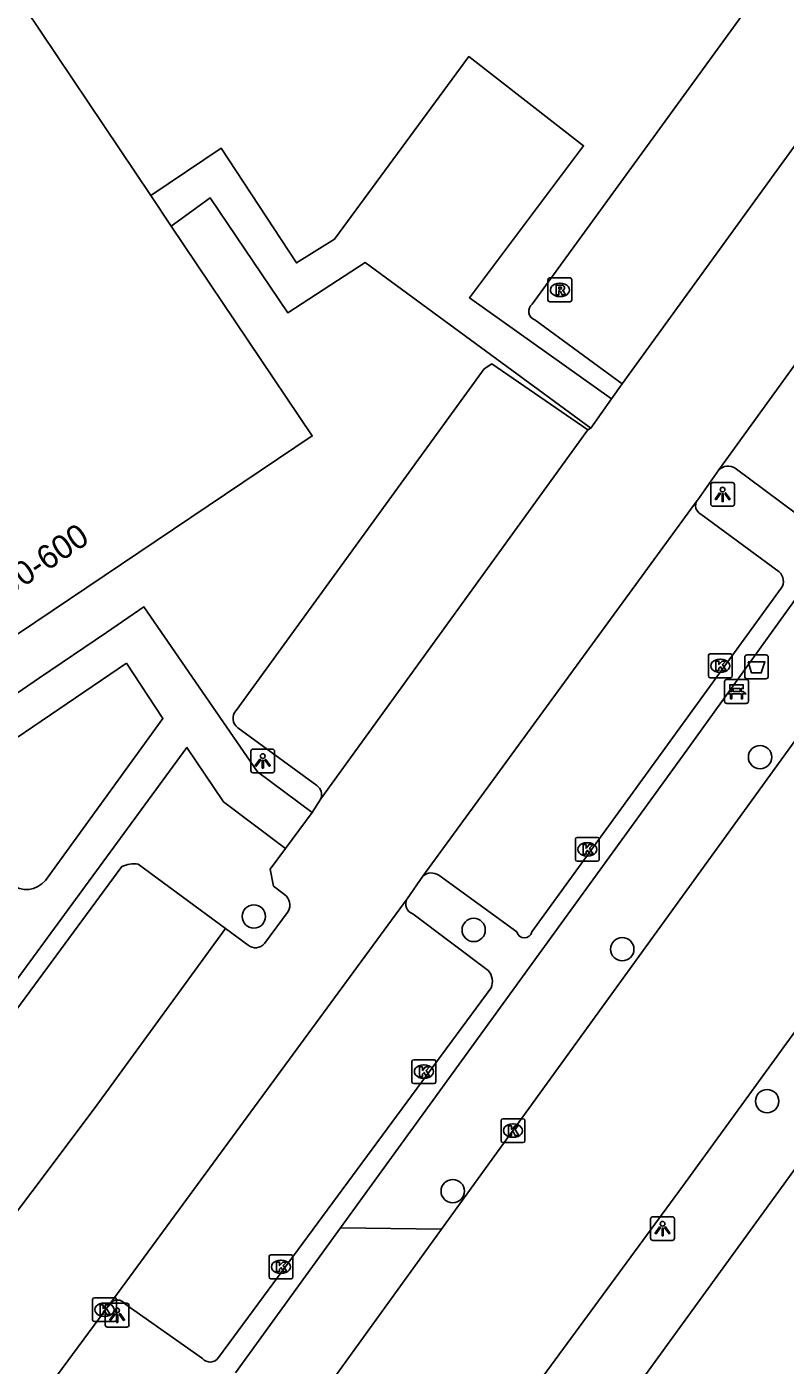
# Model space of a CAD drawing. Extents: x 159675 to 160530, y 382179 to 382901.
# Drawn here: x 159972.5 to 160004.3, y 382438.2 to 382494.4 of the extents above; entities that cross this region are included whole.
import ezdxf

# ---------------------------------------------------------------- set-up
doc = ezdxf.new("R2010")
doc.units = 0
for name, color, linetype in [('IMGEO_Afvalbak', 7, 'Continuous'), ('IMGEO_Bank', 7, 'Continuous'), ('IMGEO_Boom', 7, 'Continuous'), ('IMGEO_Kolk', 7, 'Continuous'), ('IMGEO_Lichtpunt', 7, 'Continuous'), ('IMGEO_Pand', 7, 'Continuous'), ('IMGEO_Pand_nummerreeks', 7, 'Continuous'), ('IMGEO_Parkeervlak_open', 7, 'Continuous'), ('IMGEO_Rijbaan_lokaal_open', 7, 'Continuous'), ('IMGEO_Rioolput', 7, 'Continuous'), ('IMGEO_Voetpad_gesloten', 7, 'Continuous'), ('IMGEO_Voetpad_open', 7, 'Continuous')]:
    doc.layers.add(name, color=color, linetype=linetype)

msp = doc.modelspace()

# ---------------------------------------------------------------- linework, layer by layer
at = {"layer": 'IMGEO_Afvalbak'}
for p, q in [((160002.607, 382467.102), (160002.607, 382467.902)), ((160002.607, 382467.902), (160002.607, 382467.102)), ((160002.707, 382468.002), (160003.497, 382468.002)), ((160003.497, 382468.002), (160002.707, 382468.002)), ((160003.597, 382467.902), (160003.597, 382467.102)), ((160003.597, 382467.102), (160003.597, 382467.902)), ((160003.497, 382467.002), (160002.707, 382467.002)), ((160002.707, 382467.002), (160003.497, 382467.002))]:
    msp.add_line(p, q, dxfattribs=at)
msp.add_lwpolyline([(160002.75, 382467.716), (160003.454, 382467.716), (160003.305, 382467.246), (160002.899, 382467.246), (160002.75, 382467.716)], dxfattribs=at)
for centre, start, end in [((160002.707, 382467.902), 90, 180), ((160002.707, 382467.902), 90, 180), ((160003.497, 382467.902), 0, 90), ((160003.497, 382467.902), 360, 90), ((160002.707, 382467.102), 180, 270), ((160002.707, 382467.102), 180, 270), ((160003.497, 382467.102), 270, 0), ((160003.497, 382467.102), 270, 0)]:
    msp.add_arc(centre, 0.1, start, end, dxfattribs=at)
at = {"layer": 'IMGEO_Bank'}
for p, q in [((160001.764, 382466.044), (160001.764, 382466.885)), ((160001.764, 382466.885), (160001.764, 382466.044)), ((160001.839, 382466.969), (160002.68, 382466.969)), ((160002.68, 382466.969), (160001.839, 382466.969)), ((160002.073, 382466.475), (160002.073, 382466.581)), ((160002.117, 382466.581), (160002.117, 382466.475)), ((160002.405, 382466.587), (160002.123, 382466.587)), ((160002.411, 382466.475), (160002.411, 382466.581)), ((160002.455, 382466.581), (160002.455, 382466.475)), ((160002.764, 382466.894), (160002.764, 382466.053)), ((160002.764, 382466.053), (160002.764, 382466.894)), ((160002.461, 382466.367), (160002.068, 382466.367)), ((160002.123, 382466.469), (160002.405, 382466.469)), ((160002.689, 382465.969), (160001.848, 382465.969)), ((160001.848, 382465.969), (160002.689, 382465.969))]:
    msp.add_line(p, q, dxfattribs=at)
for points in [[(160002.067, 382466.587), (160001.981, 382466.587), (160001.981, 382466.748), (160002.544, 382466.748), (160002.544, 382466.587), (160002.461, 382466.587)], [(160002.011, 382466.367), (160001.869, 382466.367), (160001.981, 382466.469), (160002.067, 382466.469)], [(160002.061, 382466.36), (160002.061, 382466.153), (160002.018, 382466.153), (160002.018, 382466.36)], [(160002.461, 382466.469), (160002.544, 382466.469), (160002.656, 382466.367), (160002.517, 382466.367)], [(160002.511, 382466.36), (160002.511, 382466.153), (160002.467, 382466.153), (160002.467, 382466.36)]]:
    msp.add_lwpolyline(points, dxfattribs=at)
for centre, radius, start, end in [((160001.842, 382466.891), 0.0779, 92.4484, 184.2845), ((160001.842, 382466.891), 0.0779, 92.4484, 184.2845), ((160002.066, 382466.58), 0.00671, 2.8957, 87.1043), ((160002.123, 382466.58), 0.00671, 92.8957, 177.1043), ((160002.405, 382466.58), 0.00671, 2.8957, 87.1043), ((160002.462, 382466.58), 0.00671, 92.8957, 177.1043), ((160002.686, 382466.891), 0.0779, 2.4484, 94.2845), ((160002.686, 382466.891), 0.0779, 2.4484, 94.2845), ((160001.842, 382466.047), 0.0779, 182.4484, 274.2845), ((160001.842, 382466.047), 0.0779, 182.4484, 274.2845), ((160002.011, 382466.36), 0.00671, 2.8957, 87.1043), ((160002.068, 382466.36), 0.00671, 92.8957, 177.1043), ((160002.066, 382466.476), 0.00671, 272.8957, 357.1043), ((160002.123, 382466.476), 0.00671, 182.8957, 267.1043), ((160002.405, 382466.476), 0.00671, 272.8957, 357.1043), ((160002.462, 382466.476), 0.00671, 182.8957, 267.1043), ((160002.46, 382466.36), 0.00671, 2.8957, 87.1043), ((160002.517, 382466.36), 0.00671, 92.8957, 177.1043), ((160002.686, 382466.047), 0.0779, 272.4484, 4.2845), ((160002.686, 382466.047), 0.0779, 272.4484, 4.2845)]:
    msp.add_arc(centre, radius, start, end, dxfattribs=at)
at = {"layer": 'IMGEO_Boom'}
for centre in [(160003.25, 382463.712), (159982.015, 382457.028), (159991.237, 382456.462), (159997.472, 382455.653), (160003.548, 382449.28), (159990.357, 382445.504)]:
    msp.add_circle(centre, 0.489, dxfattribs=at)
at = {"layer": 'IMGEO_Kolk'}
for p, q in [((160001.082, 382467.117), (160001.082, 382467.969)), ((160001.157, 382468.043), (160002.009, 382468.043)), ((160001.57, 382467.823), (160001.595, 382467.823)), ((160002.083, 382467.969), (160002.083, 382467.117)), ((160001.593, 382467.263), (160001.568, 382467.263)), ((160002.009, 382467.043), (160001.157, 382467.043)), ((159995.506, 382459.416), (159995.506, 382460.268)), ((159995.581, 382460.342), (159996.433, 382460.342)), ((159995.994, 382460.122), (159996.019, 382460.122)), ((159996.507, 382460.268), (159996.507, 382459.416)), ((159996.433, 382459.342), (159995.581, 382459.342)), ((159996.017, 382459.562), (159995.992, 382459.562)), ((159988.648, 382450.093), (159988.648, 382450.945)), ((159988.723, 382451.019), (159989.575, 382451.019)), ((159989.649, 382450.945), (159989.649, 382450.093)), ((159989.136, 382450.799), (159989.161, 382450.799)), ((159989.575, 382450.019), (159988.723, 382450.019)), ((159989.159, 382450.239), (159989.134, 382450.239)), ((159992.384, 382447.617), (159992.384, 382448.469)), ((159992.459, 382448.543), (159993.311, 382448.543)), ((159992.872, 382448.323), (159992.897, 382448.323)), ((159993.385, 382448.469), (159993.385, 382447.617)), ((159993.311, 382447.543), (159992.459, 382447.543)), ((159992.895, 382447.763), (159992.87, 382447.763)), ((159982.651, 382441.904), (159982.651, 382442.756)), ((159982.726, 382442.83), (159983.578, 382442.83)), ((159983.139, 382442.61), (159983.164, 382442.61)), ((159983.652, 382442.756), (159983.652, 382441.904)), ((159983.162, 382442.05), (159983.137, 382442.05)), ((159983.578, 382441.83), (159982.726, 382441.83)), ((159975.248, 382440.105), (159975.248, 382440.957)), ((159975.323, 382441.031), (159976.175, 382441.031)), ((159975.736, 382440.811), (159975.761, 382440.811)), ((159976.249, 382440.957), (159976.249, 382440.105)), ((159975.759, 382440.251), (159975.734, 382440.251)), ((159976.175, 382440.031), (159975.323, 382440.031))]:
    msp.add_line(p, q, dxfattribs=at)
for points in [[(160001.082, 382467.117), (160001.082, 382467.969)], [(160001.157, 382468.043), (160002.009, 382468.043)], [(160001.403, 382467.743), (160001.526, 382467.743), (160001.526, 382467.592), (160001.656, 382467.743), (160001.82, 382467.743), (160001.674, 382467.592), (160001.827, 382467.343), (160001.675, 382467.343), (160001.59, 382467.507), (160001.526, 382467.44), (160001.526, 382467.343), (160001.403, 382467.343), (160001.403, 382467.743)], [(160002.083, 382467.969), (160002.083, 382467.117)], [(160002.009, 382467.043), (160001.157, 382467.043)], [(159995.506, 382459.416), (159995.506, 382460.268)], [(159995.581, 382460.342), (159996.433, 382460.342)], [(159995.827, 382460.042), (159995.95, 382460.042), (159995.95, 382459.891), (159996.08, 382460.042), (159996.244, 382460.042), (159996.098, 382459.891), (159996.251, 382459.642), (159996.099, 382459.642), (159996.014, 382459.806), (159995.95, 382459.739), (159995.95, 382459.642), (159995.827, 382459.642), (159995.827, 382460.042)], [(159996.507, 382460.268), (159996.507, 382459.416)], [(159996.433, 382459.342), (159995.581, 382459.342)], [(159988.648, 382450.093), (159988.648, 382450.945)], [(159988.723, 382451.019), (159989.575, 382451.019)], [(159989.649, 382450.945), (159989.649, 382450.093)], [(159988.969, 382450.719), (159989.092, 382450.719), (159989.092, 382450.568), (159989.222, 382450.719), (159989.386, 382450.719), (159989.24, 382450.568), (159989.393, 382450.319), (159989.241, 382450.319), (159989.156, 382450.483), (159989.092, 382450.416), (159989.092, 382450.319), (159988.969, 382450.319), (159988.969, 382450.719)], [(159989.575, 382450.019), (159988.723, 382450.019)], [(159992.384, 382447.617), (159992.384, 382448.469)], [(159992.459, 382448.543), (159993.311, 382448.543)], [(159992.705, 382448.243), (159992.828, 382448.243), (159992.828, 382448.092), (159992.958, 382448.243), (159993.122, 382448.243), (159992.976, 382448.092), (159993.129, 382447.843), (159992.977, 382447.843), (159992.892, 382448.007), (159992.828, 382447.94), (159992.828, 382447.843), (159992.705, 382447.843), (159992.705, 382448.243)], [(159993.385, 382448.469), (159993.385, 382447.617)], [(159993.311, 382447.543), (159992.459, 382447.543)], [(159982.651, 382441.904), (159982.651, 382442.756)], [(159982.726, 382442.83), (159983.578, 382442.83)], [(159982.972, 382442.53), (159983.095, 382442.53), (159983.095, 382442.379), (159983.225, 382442.53), (159983.389, 382442.53), (159983.243, 382442.379), (159983.396, 382442.13), (159983.244, 382442.13), (159983.159, 382442.294), (159983.095, 382442.227), (159983.095, 382442.13), (159982.972, 382442.13), (159982.972, 382442.53)], [(159983.652, 382442.756), (159983.652, 382441.904)], [(159983.578, 382441.83), (159982.726, 382441.83)], [(159975.248, 382440.105), (159975.248, 382440.957)], [(159975.323, 382441.031), (159976.175, 382441.031)], [(159976.249, 382440.957), (159976.249, 382440.105)], [(159975.569, 382440.731), (159975.692, 382440.731), (159975.692, 382440.58), (159975.822, 382440.731), (159975.986, 382440.731), (159975.84, 382440.58), (159975.993, 382440.331), (159975.841, 382440.331), (159975.756, 382440.495), (159975.692, 382440.428), (159975.692, 382440.331), (159975.569, 382440.331), (159975.569, 382440.731)], [(159976.175, 382440.031), (159975.323, 382440.031)]]:
    msp.add_lwpolyline(points, dxfattribs=at)
for centre, start, end in [((160001.159, 382467.967), 91.552, 178.448), ((160001.159, 382467.967), 91.552, 178.448), ((160002.007, 382467.967), 1.552, 88.448), ((160002.007, 382467.967), 1.552, 88.448), ((160001.159, 382467.119), 181.552, 268.448), ((160001.159, 382467.119), 181.552, 268.448), ((160002.007, 382467.119), 271.552, 358.448), ((160002.007, 382467.119), 271.552, 358.448), ((159995.583, 382460.266), 91.552, 178.448), ((159995.583, 382460.266), 91.552, 178.448), ((159996.431, 382460.266), 1.552, 88.448), ((159996.431, 382460.266), 1.552, 88.448), ((159995.583, 382459.418), 181.552, 268.448), ((159995.583, 382459.418), 181.552, 268.448), ((159996.431, 382459.418), 271.552, 358.448), ((159996.431, 382459.418), 271.552, 358.448), ((159988.725, 382450.943), 91.552, 178.448), ((159988.725, 382450.943), 91.552, 178.448), ((159989.573, 382450.943), 1.552, 88.448), ((159989.573, 382450.943), 1.552, 88.448), ((159988.725, 382450.095), 181.552, 268.448), ((159988.725, 382450.095), 181.552, 268.448), ((159989.573, 382450.095), 271.552, 358.448), ((159989.573, 382450.095), 271.552, 358.448), ((159992.461, 382448.467), 91.552, 178.448), ((159992.461, 382448.467), 91.552, 178.448), ((159993.309, 382448.467), 1.552, 88.448), ((159993.309, 382448.467), 1.552, 88.448), ((159992.461, 382447.619), 181.552, 268.448), ((159992.461, 382447.619), 181.552, 268.448), ((159993.309, 382447.619), 271.552, 358.448), ((159993.309, 382447.619), 271.552, 358.448), ((159982.728, 382442.754), 91.552, 178.448), ((159982.728, 382442.754), 91.552, 178.448), ((159983.576, 382442.754), 1.552, 88.448), ((159983.576, 382442.754), 1.552, 88.448), ((159982.728, 382441.906), 181.552, 268.448), ((159982.728, 382441.906), 181.552, 268.448), ((159983.576, 382441.906), 271.552, 358.448), ((159983.576, 382441.906), 271.552, 358.448), ((159975.325, 382440.955), 91.552, 178.448), ((159975.325, 382440.955), 91.552, 178.448), ((159976.173, 382440.955), 1.552, 88.448), ((159976.173, 382440.955), 1.552, 88.448), ((159975.325, 382440.107), 181.552, 268.448), ((159975.325, 382440.107), 181.552, 268.448), ((159976.173, 382440.107), 271.552, 358.448), ((159976.173, 382440.107), 271.552, 358.448)]:
    msp.add_arc(centre, 0.0765, start, end, dxfattribs=at)
for centre, major_axis, ratio, start_param, end_param in [((160001.569, 382467.543), (-0.387, 0.002), 0.722429, 4.712389, 7.853982), ((160001.594, 382467.543), (-0.39, 0.002), 0.717154, 1.570796, 4.712389), ((159995.993, 382459.842), (-0.387, 0.002), 0.722429, 4.712389, 7.853982), ((159996.018, 382459.842), (-0.39, 0.002), 0.717154, 1.570796, 4.712389), ((159989.135, 382450.519), (-0.387, 0.002), 0.722429, 4.712389, 7.853982), ((159989.16, 382450.519), (-0.39, 0.002), 0.717154, 1.570796, 4.712389), ((159992.871, 382448.043), (-0.387, 0.002), 0.722429, 4.712389, 7.853982), ((159992.896, 382448.043), (-0.39, 0.002), 0.717154, 1.570796, 4.712389), ((159983.138, 382442.33), (-0.387, 0.002), 0.722429, 4.712389, 7.853982), ((159983.163, 382442.33), (-0.39, 0.002), 0.717154, 1.570796, 4.712389), ((159975.735, 382440.531), (-0.387, 0.002), 0.722429, 4.712389, 7.853982), ((159975.76, 382440.531), (-0.39, 0.002), 0.717154, 1.570796, 4.712389)]:
    msp.add_ellipse(centre, major_axis=major_axis, ratio=ratio, start_param=start_param, end_param=end_param, dxfattribs=at)
at = {"layer": 'IMGEO_Lichtpunt'}
for p, q in [((160001.181, 382475.138), (160001.181, 382474.331)), ((160001.181, 382475.138), (160001.181, 382474.331)), ((160002.083, 382475.233), (160001.275, 382475.233)), ((160002.083, 382475.233), (160001.275, 382475.233)), ((160002.177, 382474.331), (160002.177, 382475.138)), ((160002.177, 382474.331), (160002.177, 382475.138)), ((160001.275, 382474.237), (160002.083, 382474.237)), ((160001.275, 382474.237), (160002.083, 382474.237)), ((159981.89, 382463.956), (159981.89, 382463.149)), ((159981.89, 382463.956), (159981.89, 382463.149)), ((159982.792, 382464.051), (159981.984, 382464.051)), ((159982.792, 382464.051), (159981.984, 382464.051)), ((159982.886, 382463.149), (159982.886, 382463.956)), ((159982.886, 382463.149), (159982.886, 382463.956)), ((159981.984, 382463.055), (159982.792, 382463.055)), ((159981.984, 382463.055), (159982.792, 382463.055)), ((159998.662, 382444.338), (159998.662, 382443.531)), ((159998.662, 382444.338), (159998.662, 382443.531)), ((159999.564, 382444.433), (159998.756, 382444.433)), ((159999.564, 382444.433), (159998.756, 382444.433)), ((159999.658, 382443.531), (159999.658, 382444.338)), ((159999.658, 382443.531), (159999.658, 382444.338)), ((159998.756, 382443.437), (159999.564, 382443.437)), ((159998.756, 382443.437), (159999.564, 382443.437)), ((159976.683, 382440.798), (159975.875, 382440.798)), ((159976.683, 382440.798), (159975.875, 382440.798)), ((159975.781, 382440.703), (159975.781, 382439.896)), ((159975.781, 382440.703), (159975.781, 382439.896)), ((159976.777, 382439.896), (159976.777, 382440.703)), ((159976.777, 382439.896), (159976.777, 382440.703)), ((159975.875, 382439.802), (159976.683, 382439.802)), ((159975.875, 382439.802), (159976.683, 382439.802))]:
    msp.add_line(p, q, dxfattribs=at)
for points in [[(160001.555, 382474.802), (160001.594, 382474.774), (160001.406, 382474.512), (160001.368, 382474.539), (160001.555, 382474.802)], [(160001.657, 382474.754), (160001.704, 382474.754), (160001.704, 382474.432), (160001.657, 382474.432), (160001.657, 382474.754)], [(160001.767, 382474.774), (160001.805, 382474.801), (160001.992, 382474.539), (160001.953, 382474.511), (160001.767, 382474.774)], [(159982.264, 382463.62), (159982.303, 382463.592), (159982.115, 382463.33), (159982.077, 382463.357), (159982.264, 382463.62)], [(159982.366, 382463.572), (159982.413, 382463.572), (159982.413, 382463.25), (159982.366, 382463.25), (159982.366, 382463.572)], [(159982.476, 382463.592), (159982.514, 382463.619), (159982.701, 382463.357), (159982.662, 382463.329), (159982.476, 382463.592)], [(159999.036, 382444.002), (159999.075, 382443.974), (159998.887, 382443.712), (159998.849, 382443.739), (159999.036, 382444.002)], [(159999.138, 382443.954), (159999.185, 382443.954), (159999.185, 382443.632), (159999.138, 382443.632), (159999.138, 382443.954)], [(159999.248, 382443.974), (159999.286, 382444.001), (159999.473, 382443.739), (159999.434, 382443.711), (159999.248, 382443.974)], [(159976.155, 382440.367), (159976.194, 382440.339), (159976.006, 382440.077), (159975.968, 382440.104), (159976.155, 382440.367)], [(159976.257, 382440.319), (159976.304, 382440.319), (159976.304, 382439.997), (159976.257, 382439.997), (159976.257, 382440.319)], [(159976.367, 382440.339), (159976.405, 382440.366), (159976.592, 382440.104), (159976.553, 382440.076), (159976.367, 382440.339)]]:
    msp.add_lwpolyline(points, dxfattribs=at)
for centre in [(160001.68, 382474.936), (159982.389, 382463.754), (159999.161, 382444.136), (159976.28, 382440.501)]:
    msp.add_circle(centre, 0.0994, dxfattribs=at)
for centre, start, end in [((160001.275, 382475.138), 90, 180), ((160001.275, 382475.138), 90, 180), ((160002.083, 382475.138), 0, 90), ((160002.083, 382475.138), 0, 90), ((160001.275, 382474.331), 180, 270), ((160001.275, 382474.331), 180, 270), ((160002.083, 382474.331), 270, 0), ((160002.083, 382474.331), 270, 360), ((159981.984, 382463.956), 90, 180), ((159981.984, 382463.956), 90, 180), ((159982.792, 382463.956), 0, 90), ((159982.792, 382463.956), 0, 90), ((159981.984, 382463.149), 180, 270), ((159981.984, 382463.149), 180, 270), ((159982.792, 382463.149), 270, 0), ((159982.792, 382463.149), 270, 360), ((159998.756, 382444.338), 90, 180), ((159998.756, 382444.338), 90, 180), ((159999.564, 382444.338), 0, 90), ((159999.564, 382444.338), 0, 90), ((159998.756, 382443.531), 180, 270), ((159998.756, 382443.531), 180, 270), ((159999.564, 382443.531), 270, 0), ((159999.564, 382443.531), 270, 360), ((159975.875, 382440.703), 90, 180), ((159975.875, 382440.703), 90, 180), ((159976.683, 382440.703), 0, 90), ((159976.683, 382440.703), 0, 90), ((159975.875, 382439.896), 180, 270), ((159975.875, 382439.896), 180, 270), ((159976.683, 382439.896), 270, 0), ((159976.683, 382439.896), 270, 360)]:
    msp.add_arc(centre, 0.0946, start, end, dxfattribs=at)
at = {"layer": 'IMGEO_Pand'}
for points in [[(159953.275, 382483.094), (159952.337, 382484.474), (159971.108, 382497.075), (159977.69, 382487.272)], [(159978.552, 382485.987), (159977.69, 382487.272)], [(159978.552, 382485.987), (159984.462, 382477.186), (159972.103, 382468.865), (159965.701, 382464.59), (159959.223, 382474.207)]]:
    msp.add_lwpolyline(points, dxfattribs=at)
at = {"layer": 'IMGEO_Parkeervlak_open'}
for points in [[(159993.697, 382482.721), (160004.104, 382497.066)], [(159997.466, 382479.378), (159993.807, 382482.054)], [(159996.032, 382477.439), (159991.992, 382480.211), (159991.678, 382480.008), (159981.273, 382465.667)], [(160005.388, 382473.465), (160002.211, 382475.832)], [(160004.053, 382471.48), (160000.766, 382473.907)], [(159993.682, 382456.376), (160004.14, 382470.802)], [(159981.347, 382464.948), (159984.655, 382462.522)], [(159976.477, 382459.119), (159966.518, 382445.61)], [(159980.82, 382456.527), (159977.165, 382459.225)], [(159989.773, 382458.761), (159993.043, 382456.381)], [(159991.844, 382454.766), (159988.686, 382457.137)], [(159980.537, 382438.524), (159991.968, 382454.03)], [(159976.606, 382440.776), (159979.862, 382438.479)]]:
    msp.add_lwpolyline(points, dxfattribs=at)
for centre, radius, start, end in [((159993.933, 382482.417), 0.384, 127.8031, 250.9265), ((160001.907, 382475.331), 0.586, 58.7458, 131.7769), ((160000.944, 382474.26), 0.395, 146.4119, 243.2135), ((160003.725, 382471.093), 0.507, 324.9413, 49.6831), ((159981.608, 382465.338), 0.469, 135.4859, 236.2666), ((159984.385, 382462.135), 0.472, 339.1728, 55.0762), ((159976.987, 382458.095), 1.144, 81.0385, 116.4788), ((159989.467, 382458.298), 0.555, 56.5201, 130.0406), ((159988.817, 382457.551), 0.434, 150.1035, 252.3975), ((159993.363, 382456.455), 0.329, 193.0004, 346.1029), ((159991.318, 382454.299), 0.703, 337.5039, 41.6227), ((159976.293, 382440.551), 0.386, 35.705, 140.7386), ((159980.182, 382438.762), 0.427, 221.4849, 326.1432)]:
    msp.add_arc(centre, radius, start, end, dxfattribs=at)
at = {"layer": 'IMGEO_Rijbaan_lokaal_open'}
for points in [[(160008.707, 382494.883), (159997.466, 382479.378)], [(160001.516, 382475.768), (160012.741, 382491.261)], [(159989.893, 382443.905), (160000, 382457.874), (160020.333, 382485.978)], [(159997.466, 382479.378), (159997.019, 382478.745)], [(159997.019, 382478.745), (159996.152, 382477.512)], [(159996.032, 382477.439), (159984.826, 382461.967)], [(159996.152, 382477.512), (159996.032, 382477.439)], [(160000.615, 382474.478), (160000.638, 382474.511), (160001.516, 382475.768)], [(159989.11, 382458.723), (160000.615, 382474.478)], [(159984.826, 382461.967), (159984.461, 382461.389)], [(159984.461, 382461.389), (159983.343, 382459.872)], [(159983.343, 382459.872), (159982.702, 382459.015), (159982.838, 382458.301), (159983.301, 382457.947)], [(159988.441, 382457.767), (159989.11, 382458.723)], [(159975.994, 382440.795), (159988.441, 382457.767)], [(159983.452, 382457.239), (159982.467, 382455.892)], [(159980.82, 382456.527), (159975.319, 382448.954), (159970.077, 382441.998)], [(159981.771, 382455.825), (159980.82, 382456.527)], [(159984.695, 382424.782), (159986.94, 382427.882), (159990.318, 382432.531), (160000, 382445.699), (160006.199, 382454.224)], [(159989.893, 382443.905), (159982.977, 382434.345)], [(159970.361, 382433.202), (159975.994, 382440.795)]]:
    msp.add_lwpolyline(points, dxfattribs=at)
for centre, radius, start, end in [((159982.986, 382457.51), 0.539, 329.8738, 54.2051), ((159982.085, 382456.216), 0.502, 231.3059, 319.6912)]:
    msp.add_arc(centre, radius, start, end, dxfattribs=at)
at = {"layer": 'IMGEO_Rioolput'}
for p, q in [((159994.354, 382482.887), (159994.354, 382483.739)), ((159994.429, 382483.813), (159995.281, 382483.813)), ((159994.842, 382483.593), (159994.867, 382483.593)), ((159995.355, 382483.739), (159995.355, 382482.887)), ((159994.865, 382483.033), (159994.84, 382483.033)), ((159995.281, 382482.813), (159994.429, 382482.813))]:
    msp.add_line(p, q, dxfattribs=at)
for points in [[(159994.354, 382482.887), (159994.354, 382483.739)], [(159994.429, 382483.813), (159995.281, 382483.813)], [(159994.943, 382483.511), (159994.691, 382483.513), (159994.691, 382483.113)], [(159994.869, 382483.432), (159994.815, 382483.432), (159994.815, 382483.351)], [(159995.355, 382483.739), (159995.355, 382482.887)], [(159994.691, 382483.113), (159994.815, 382483.113), (159994.815, 382483.275), (159994.826, 382483.275)], [(159994.815, 382483.351), (159994.867, 382483.351)], [(159994.873, 382483.246), (159994.944, 382483.113), (159995.084, 382483.113), (159995.019, 382483.239)], [(159995.281, 382482.813), (159994.429, 382482.813)]]:
    msp.add_lwpolyline(points, dxfattribs=at)
for centre, radius, start, end in [((159994.431, 382483.737), 0.0765, 91.552, 178.448), ((159994.431, 382483.737), 0.0765, 91.552, 178.448), ((159994.875, 382483.336), 0.0964, 77.0061, 93.1865), ((159994.889, 382483.393), 0.0378, 276.6634, 79.6772), ((159994.942, 382483.401), 0.109, 350.3612, 89.416), ((159995.279, 382483.737), 0.0765, 1.552, 88.448), ((159995.279, 382483.737), 0.0765, 1.552, 88.448), ((159994.431, 382482.889), 0.0765, 181.552, 268.448), ((159994.431, 382482.889), 0.0765, 181.552, 268.448), ((159994.825, 382483.222), 0.0533, 26.0293, 88.6989), ((159994.851, 382483.54), 0.19, 274.7715, 282.9687), ((159994.94, 382483.401), 0.112, 277.5842, 350.9817), ((159994.924, 382483.186), 0.108, 29.5134, 73.7905), ((159995.279, 382482.889), 0.0765, 271.552, 358.448), ((159995.279, 382482.889), 0.0765, 271.552, 358.448)]:
    msp.add_arc(centre, radius, start, end, dxfattribs=at)
for centre, major_axis, ratio, start_param, end_param in [((159994.841, 382483.313), (-0.387, 0.002), 0.722429, 4.712389, 7.853982), ((159994.866, 382483.313), (-0.39, 0.002), 0.717154, 1.570796, 4.712389)]:
    msp.add_ellipse(centre, major_axis=major_axis, ratio=ratio, start_param=start_param, end_param=end_param, dxfattribs=at)
at = {"layer": 'IMGEO_Voetpad_gesloten'}
for points in [[(159984.461, 382461.389), (159982.172, 382463.099), (159977.404, 382470.015), (159975.834, 382468.946), (159973.024, 382467.034), (159966.95, 382462.888), (159971.088, 382456.766)], [(159969.893, 382463.06), (159976.672, 382467.661)], [(159976.672, 382467.661), (159978.195, 382465.338), (159973.27, 382458.541)], [(159962.528, 382441.377), (159979.204, 382464.122), (159980.738, 382461.834), (159983.343, 382459.872)]]:
    msp.add_lwpolyline(points, dxfattribs=at)
msp.add_arc((159972.466, 382459.191), 1.034, 231.4326, 321.0219, dxfattribs=at)
at = {"layer": 'IMGEO_Voetpad_open'}
for points in [[(159977.69, 382487.272), (159980.642, 382489.262), (159983.802, 382484.443), (159985.395, 382485.449), (159991.028, 382493.103), (159995.849, 382489.364), (159991.06, 382482.986), (159997.019, 382478.745)], [(160017.37, 382487.892), (160000, 382463.753), (159985.646, 382443.958)], [(159996.152, 382477.512), (159986.689, 382484.462), (159983.444, 382482.349), (159980.187, 382487.175), (159978.552, 382485.987)], [(160009.446, 382452.95), (160000, 382439.936), (159979.481, 382411.665)], [(159981.244, 382437.887), (159985.646, 382443.958)], [(159985.646, 382443.958), (159989.893, 382443.905)]]:
    msp.add_lwpolyline(points, dxfattribs=at)

# ---------------------------------------------------------------- texts
at = {"layer": 'IMGEO_Pand_nummerreeks'}
msp.add_text('90-600', height=1, rotation=33.952, dxfattribs=at).set_placement((159971.728, 382470.421))

doc.saveas('drawing.dxf')
